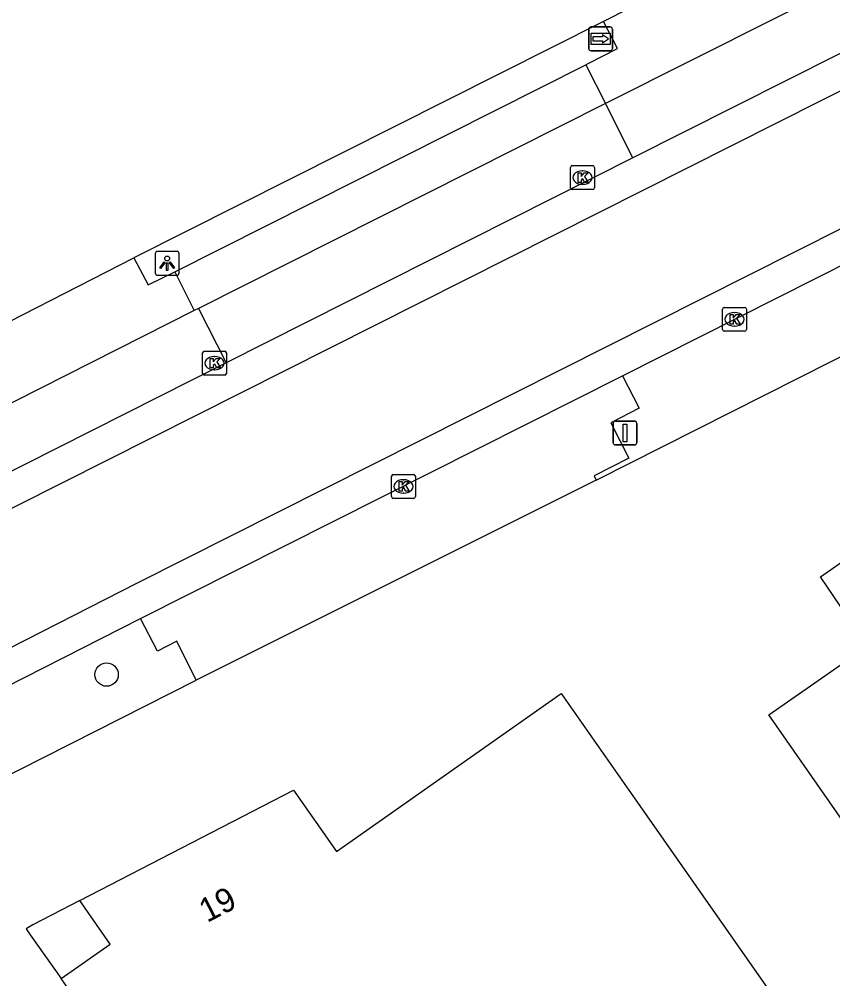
# Model space of a CAD drawing. Extents: x 156651 to 158072, y 387631 to 388990.
# Drawn here: x 157175.66 to 157209.72, y 388302.52 to 388342.68 of the extents above; entities that cross this region are included whole.
import ezdxf

# ---------------------------------------------------------------- set-up
doc = ezdxf.new("R2010")
doc.units = 0
for name, color, linetype in [('IMGEO_Berm_groen', 7, 'Continuous'), ('IMGEO_Boom', 7, 'Continuous'), ('IMGEO_Groenvoorziening', 7, 'Continuous'), ('IMGEO_Kolk', 7, 'Continuous'), ('IMGEO_Lichtpunt', 7, 'Continuous'), ('IMGEO_Pand', 7, 'Continuous'), ('IMGEO_Pand_nummerreeks', 7, 'Continuous'), ('IMGEO_Pand_overbouw', 7, 'Continuous'), ('IMGEO_Parkeervlak_gesloten', 7, 'Continuous'), ('IMGEO_Rijbaan_lokaal_gesloten', 7, 'Continuous'), ('IMGEO_Rijbaan_lokaal_open', 7, 'Continuous'), ('IMGEO_Verkeersbordpaal', 7, 'Continuous'), ('IMGEO_Voetpad_open', 7, 'Continuous'), ('IMGEO_Wegwijzer', 7, 'Continuous')]:
    doc.layers.add(name, color=color, linetype=linetype)

msp = doc.modelspace()

# ---------------------------------------------------------------- linework, layer by layer
at = {"layer": 'IMGEO_Berm_groen'}
for points in [[(157199.814, 388323.396), (157222.36, 388334.779)], [(157174.598, 388310.74), (157183.072, 388315.021)]]:
    msp.add_lwpolyline(points, dxfattribs=at)
at = {"layer": 'IMGEO_Boom'}
msp.add_circle((157179.32, 388315.257), 0.489, dxfattribs=at)
at = {"layer": 'IMGEO_Groenvoorziening'}
msp.add_lwpolyline([(157200.119, 388342.587), (157180.461, 388332.701)], dxfattribs=at)
at = {"layer": 'IMGEO_Kolk'}
for p, q in [((157198.738, 388335.628), (157198.738, 388336.48)), ((157198.813, 388336.554), (157199.665, 388336.554)), ((157199.739, 388336.48), (157199.739, 388335.628)), ((157199.226, 388336.334), (157199.251, 388336.334)), ((157199.665, 388335.554), (157198.813, 388335.554)), ((157199.249, 388335.774), (157199.224, 388335.774)), ((157205.101, 388329.697), (157205.101, 388330.549)), ((157205.176, 388330.623), (157206.028, 388330.623)), ((157205.589, 388330.403), (157205.614, 388330.403)), ((157206.102, 388330.549), (157206.102, 388329.697)), ((157206.028, 388329.623), (157205.176, 388329.623)), ((157205.612, 388329.843), (157205.587, 388329.843)), ((157183.411, 388328.789), (157184.263, 388328.789)), ((157183.336, 388327.863), (157183.336, 388328.715)), ((157183.824, 388328.569), (157183.849, 388328.569)), ((157184.337, 388328.715), (157184.337, 388327.863)), ((157183.847, 388328.009), (157183.822, 388328.009)), ((157184.263, 388327.789), (157183.411, 388327.789)), ((157191.245, 388322.704), (157191.245, 388323.556)), ((157191.32, 388323.63), (157192.172, 388323.63)), ((157192.246, 388323.556), (157192.246, 388322.704)), ((157191.733, 388323.41), (157191.758, 388323.41)), ((157191.756, 388322.85), (157191.731, 388322.85)), ((157192.172, 388322.63), (157191.32, 388322.63))]:
    msp.add_line(p, q, dxfattribs=at)
for points in [[(157198.738, 388335.628), (157198.738, 388336.48)], [(157198.813, 388336.554), (157199.665, 388336.554)], [(157199.739, 388336.48), (157199.739, 388335.628)], [(157199.059, 388336.254), (157199.182, 388336.254), (157199.182, 388336.103), (157199.312, 388336.254), (157199.476, 388336.254), (157199.33, 388336.103), (157199.483, 388335.854), (157199.331, 388335.854), (157199.246, 388336.018), (157199.182, 388335.951), (157199.182, 388335.854), (157199.059, 388335.854), (157199.059, 388336.254)], [(157199.665, 388335.554), (157198.813, 388335.554)], [(157205.101, 388329.697), (157205.101, 388330.549)], [(157205.176, 388330.623), (157206.028, 388330.623)], [(157206.102, 388330.549), (157206.102, 388329.697)], [(157205.422, 388330.323), (157205.545, 388330.323), (157205.545, 388330.172), (157205.675, 388330.323), (157205.839, 388330.323), (157205.693, 388330.172), (157205.846, 388329.923), (157205.694, 388329.923), (157205.609, 388330.087), (157205.545, 388330.02), (157205.545, 388329.923), (157205.422, 388329.923), (157205.422, 388330.323)], [(157206.028, 388329.623), (157205.176, 388329.623)], [(157183.411, 388328.789), (157184.263, 388328.789)], [(157183.336, 388327.863), (157183.336, 388328.715)], [(157183.657, 388328.489), (157183.78, 388328.489), (157183.78, 388328.338), (157183.91, 388328.489), (157184.074, 388328.489), (157183.928, 388328.338), (157184.081, 388328.089), (157183.929, 388328.089), (157183.844, 388328.253), (157183.78, 388328.186), (157183.78, 388328.089), (157183.657, 388328.089), (157183.657, 388328.489)], [(157184.337, 388328.715), (157184.337, 388327.863)], [(157184.263, 388327.789), (157183.411, 388327.789)], [(157191.245, 388322.704), (157191.245, 388323.556)], [(157191.32, 388323.63), (157192.172, 388323.63)], [(157192.246, 388323.556), (157192.246, 388322.704)], [(157191.566, 388323.33), (157191.689, 388323.33), (157191.689, 388323.179), (157191.819, 388323.33), (157191.983, 388323.33), (157191.837, 388323.179), (157191.99, 388322.93), (157191.838, 388322.93), (157191.753, 388323.094), (157191.689, 388323.027), (157191.689, 388322.93), (157191.566, 388322.93), (157191.566, 388323.33)], [(157192.172, 388322.63), (157191.32, 388322.63)]]:
    msp.add_lwpolyline(points, dxfattribs=at)
for centre, start, end in [((157198.815, 388336.478), 91.552, 178.448), ((157198.815, 388336.478), 91.552, 178.448), ((157199.663, 388336.478), 1.552, 88.448), ((157199.663, 388336.478), 1.552, 88.448), ((157198.815, 388335.63), 181.552, 268.448), ((157198.815, 388335.63), 181.552, 268.448), ((157199.663, 388335.63), 271.552, 358.448), ((157199.663, 388335.63), 271.552, 358.448), ((157205.178, 388330.547), 91.552, 178.448), ((157205.178, 388330.547), 91.552, 178.448), ((157206.026, 388330.547), 1.552, 88.448), ((157206.026, 388330.547), 1.552, 88.448), ((157205.178, 388329.699), 181.552, 268.448), ((157205.178, 388329.699), 181.552, 268.448), ((157206.026, 388329.699), 271.552, 358.448), ((157206.026, 388329.699), 271.552, 358.448), ((157183.413, 388328.713), 91.552, 178.448), ((157183.413, 388328.713), 91.552, 178.448), ((157184.261, 388328.713), 1.552, 88.448), ((157184.261, 388328.713), 1.552, 88.448), ((157183.413, 388327.865), 181.552, 268.448), ((157183.413, 388327.865), 181.552, 268.448), ((157184.261, 388327.865), 271.552, 358.448), ((157184.261, 388327.865), 271.552, 358.448), ((157191.322, 388323.554), 91.552, 178.448), ((157191.322, 388323.554), 91.552, 178.448), ((157192.17, 388323.554), 1.552, 88.448), ((157192.17, 388323.554), 1.552, 88.448), ((157191.322, 388322.706), 181.552, 268.448), ((157191.322, 388322.706), 181.552, 268.448), ((157192.17, 388322.706), 271.552, 358.448), ((157192.17, 388322.706), 271.552, 358.448)]:
    msp.add_arc(centre, 0.0765, start, end, dxfattribs=at)
for centre, major_axis, ratio, start_param, end_param in [((157199.225, 388336.054), (-0.387, 0.002), 0.722429, 4.712389, 7.853982), ((157199.25, 388336.054), (-0.39, 0.002), 0.717154, 1.570796, 4.712389), ((157205.588, 388330.123), (-0.387, 0.002), 0.722429, 4.712389, 7.853982), ((157205.613, 388330.123), (-0.39, 0.002), 0.717154, 1.570796, 4.712389), ((157183.823, 388328.289), (-0.387, 0.002), 0.722429, 4.712389, 7.853982), ((157183.848, 388328.289), (-0.39, 0.002), 0.717154, 1.570796, 4.712389), ((157191.732, 388323.13), (-0.387, 0.002), 0.722429, 4.712389, 7.853982), ((157191.757, 388323.13), (-0.39, 0.002), 0.717154, 1.570796, 4.712389)]:
    msp.add_ellipse(centre, major_axis=major_axis, ratio=ratio, start_param=start_param, end_param=end_param, dxfattribs=at)
at = {"layer": 'IMGEO_Lichtpunt'}
for p, q in [((157181.354, 388332.871), (157181.354, 388332.064)), ((157181.354, 388332.871), (157181.354, 388332.064)), ((157182.256, 388332.966), (157181.448, 388332.966)), ((157182.256, 388332.966), (157181.448, 388332.966)), ((157182.35, 388332.064), (157182.35, 388332.871)), ((157182.35, 388332.064), (157182.35, 388332.871)), ((157181.448, 388331.97), (157182.256, 388331.97)), ((157181.448, 388331.97), (157182.256, 388331.97))]:
    msp.add_line(p, q, dxfattribs=at)
for points in [[(157181.728, 388332.535), (157181.767, 388332.507), (157181.579, 388332.245), (157181.541, 388332.272), (157181.728, 388332.535)], [(157181.83, 388332.487), (157181.877, 388332.487), (157181.877, 388332.165), (157181.83, 388332.165), (157181.83, 388332.487)], [(157181.94, 388332.507), (157181.978, 388332.534), (157182.165, 388332.272), (157182.126, 388332.244), (157181.94, 388332.507)]]:
    msp.add_lwpolyline(points, dxfattribs=at)
msp.add_circle((157181.853, 388332.669), 0.0994, dxfattribs=at)
for centre, start, end in [((157181.448, 388332.871), 90, 180), ((157181.448, 388332.871), 90, 180), ((157182.256, 388332.871), 0, 90), ((157182.256, 388332.871), 0, 90), ((157181.448, 388332.064), 180, 270), ((157181.448, 388332.064), 180, 270), ((157182.256, 388332.064), 270, 0), ((157182.256, 388332.064), 270, 360)]:
    msp.add_arc(centre, 0.0946, start, end, dxfattribs=at)
at = {"layer": 'IMGEO_Pand'}
for points in [[(157221.636, 388292.685), (157209.901, 388309.471), (157207.036, 388313.568), (157211.174, 388316.441), (157209.2, 388319.351), (157213.545, 388322.37), (157214.133, 388321.521), (157217.975, 388324.161), (157217.382, 388325.047), (157221.715, 388328.093), (157223.723, 388325.208), (157227.881, 388328.096), (157230.772, 388324.002), (157234.509, 388326.621), (157234.43, 388326.764), (157234.793, 388326.999), (157237.656, 388322.9), (157246.632, 388310.052), (157221.636, 388292.685)], [(157189.199, 388285.691), (157177.415, 388302.539), (157179.467, 388303.97), (157178.197, 388305.797), (157187.143, 388310.419), (157188.937, 388307.859), (157198.347, 388314.459), (157201.175, 388310.421), (157208.838, 388299.477)]]:
    msp.add_lwpolyline(points, dxfattribs=at)
at = {"layer": 'IMGEO_Pand_overbouw'}
msp.add_lwpolyline([(157178.197, 388305.797), (157176.225, 388304.786), (157175.958, 388304.613), (157176.121, 388304.363), (157177.415, 388302.539), (157179.467, 388303.97)], close=True, dxfattribs=at)
at = {"layer": 'IMGEO_Parkeervlak_gesloten'}
for points in [[(157200.913, 388327.752), (157218.736, 388336.736)], [(157172.657, 388313.508), (157180.743, 388317.597)]]:
    msp.add_lwpolyline(points, dxfattribs=at)
at = {"layer": 'IMGEO_Rijbaan_lokaal_gesloten'}
for points in [[(157427.649, 388413.564), (157313.182, 388386.746), (157307.564, 388385.322), (157304.11, 388384.347), (157298.594, 388382.628), (157295.094, 388381.431), (157289.829, 388379.374), (157285.802, 388377.632), (157280.387, 388375.114), (157169.957, 388319.498), (157169.378, 388320.773)], [(157171.244, 388314.319), (157180.605, 388319.095), (157279.127, 388368.703), (157285.498, 388371.81), (157294.645, 388375.709), (157303.766, 388378.867), (157314.242, 388381.65), (157428.83, 388408.527)], [(157212.051, 388342.27), (157201.348, 388336.878)], [(157201.348, 388336.878), (157184.317, 388328.298)], [(157184.317, 388328.298), (157174.441, 388323.323)]]:
    msp.add_lwpolyline(points, dxfattribs=at)
at = {"layer": 'IMGEO_Rijbaan_lokaal_open'}
for points in [[(157180.743, 388317.597), (157200.913, 388327.752)], [(157200.913, 388327.752), (157201.617, 388326.399), (157200.425, 388325.795), (157201.173, 388324.315), (157199.731, 388323.57), (157199.814, 388323.396)], [(157199.814, 388323.396), (157183.072, 388315.021)], [(157183.072, 388315.021), (157182.262, 388316.648), (157181.445, 388316.239), (157180.743, 388317.597)]]:
    msp.add_lwpolyline(points, dxfattribs=at)
at = {"layer": 'IMGEO_Verkeersbordpaal'}
for p, q in [((157200.52, 388324.966), (157200.52, 388325.766)), ((157200.52, 388325.766), (157200.52, 388324.966)), ((157200.62, 388325.866), (157201.41, 388325.866)), ((157201.41, 388325.866), (157200.62, 388325.866)), ((157201.51, 388325.766), (157201.51, 388324.966)), ((157201.51, 388324.966), (157201.51, 388325.766)), ((157201.41, 388324.866), (157200.62, 388324.866)), ((157200.62, 388324.866), (157201.41, 388324.866))]:
    msp.add_line(p, q, dxfattribs=at)
msp.add_lwpolyline([(157200.94, 388325.741), (157201.09, 388325.741), (157201.09, 388324.991), (157200.94, 388324.991), (157200.94, 388325.741)], dxfattribs=at)
for centre, start, end in [((157200.62, 388325.766), 90, 180), ((157200.62, 388325.766), 90, 180), ((157201.41, 388325.766), 0, 90), ((157201.41, 388325.766), 360, 90), ((157200.62, 388324.966), 180, 270), ((157200.62, 388324.966), 180, 270), ((157201.41, 388324.966), 270, 0), ((157201.41, 388324.966), 270, 0)]:
    msp.add_arc(centre, 0.1, start, end, dxfattribs=at)
at = {"layer": 'IMGEO_Voetpad_open'}
for points in [[(157208.141, 388346.681), (157206.748, 388345.97), (157202.298, 388343.699), (157200.119, 388342.587)], [(157210.905, 388344.546), (157200.2, 388339.156)], [(157199.382, 388340.78), (157199.48, 388340.829), (157200.712, 388341.452), (157200.119, 388342.587)], [(157182.179, 388332.106), (157199.382, 388340.78)], [(157199.382, 388340.78), (157200.2, 388339.156)], [(157200.2, 388339.156), (157183.169, 388330.579)], [(157201.348, 388336.878), (157200.2, 388339.156)], [(157174.095, 388329.453), (157180.461, 388332.701)], [(157180.461, 388332.701), (157181.053, 388331.56), (157182.179, 388332.106)], [(157182.179, 388332.106), (157182.987, 388330.487)], [(157182.987, 388330.487), (157173.295, 388325.591)], [(157183.169, 388330.579), (157182.987, 388330.487)], [(157183.169, 388330.579), (157184.317, 388328.298)]]:
    msp.add_lwpolyline(points, dxfattribs=at)
at = {"layer": 'IMGEO_Wegwijzer'}
for p, q in [((157199.503, 388341.46), (157199.503, 388342.26)), ((157199.503, 388342.26), (157199.503, 388341.46)), ((157199.603, 388342.36), (157200.393, 388342.36)), ((157200.393, 388342.36), (157199.603, 388342.36)), ((157200.493, 388342.26), (157200.493, 388341.46)), ((157200.493, 388341.46), (157200.493, 388342.26)), ((157200.393, 388341.36), (157199.603, 388341.36)), ((157199.603, 388341.36), (157200.393, 388341.36))]:
    msp.add_line(p, q, dxfattribs=at)
for points in [[(157199.604, 388342.092), (157200.392, 388342.092), (157200.392, 388341.628), (157199.604, 388341.628), (157199.604, 388342.092)], [(157199.669, 388341.944), (157199.669, 388341.86), (157199.669, 388341.776), (157200.08, 388341.776), (157200.08, 388341.693), (157200.327, 388341.86), (157200.08, 388342.027), (157200.08, 388341.944), (157199.669, 388341.944)]]:
    msp.add_lwpolyline(points, dxfattribs=at)
for centre, start, end in [((157199.603, 388342.26), 90, 180), ((157199.603, 388342.26), 90, 180), ((157200.393, 388342.26), 0, 90), ((157200.393, 388342.26), 360, 90), ((157199.603, 388341.46), 180, 270), ((157199.603, 388341.46), 180, 270), ((157200.393, 388341.46), 270, 0), ((157200.393, 388341.46), 270, 0)]:
    msp.add_arc(centre, 0.1, start, end, dxfattribs=at)

# ---------------------------------------------------------------- texts
at = {"layer": 'IMGEO_Pand_nummerreeks'}
msp.add_text('19', height=1, rotation=27.3234, dxfattribs=at).set_placement((157183.522, 388304.857))

doc.saveas('drawing.dxf')
